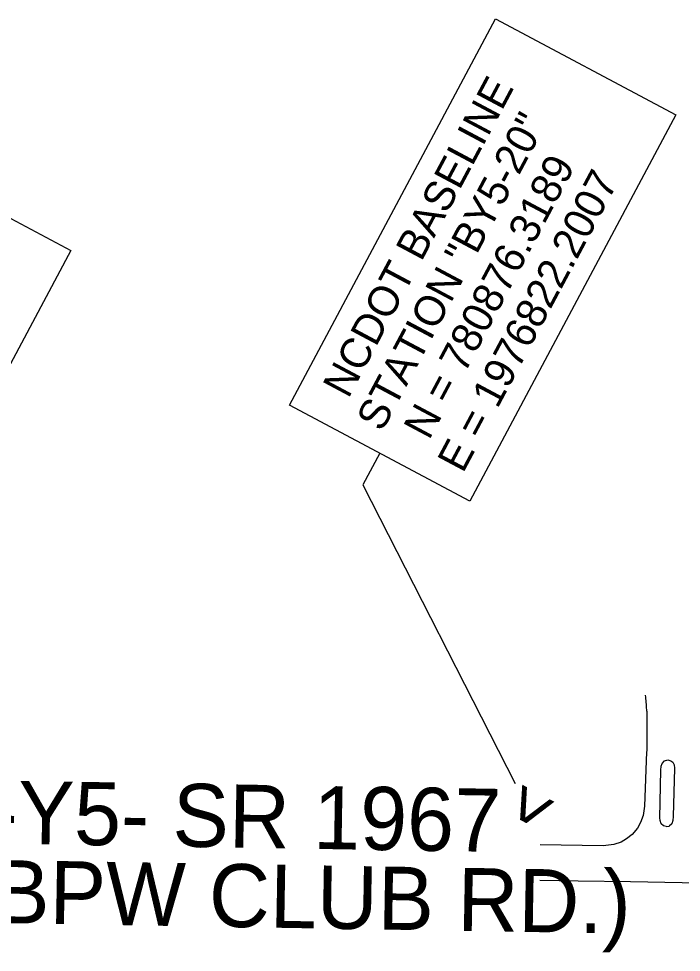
# Model space of a CAD drawing. Extents: x 1970823 to 1988115, y 770601 to 786368.
# Drawn here: x 1976409 to 1976934, y 780788 to 781528 of the extents above; entities that cross this region are included whole.
import ezdxf

# ---------------------------------------------------------------- set-up
doc = ezdxf.new("R2010")
doc.units = 0
for name, color, linetype in [('CTL Sheet Text', 7, 'Continuous'), ('CTL Supplemental Horizontal and Vertical Text', 7, 'Continuous'), ('Default', 7, 'Continuous'), ('Old_Level_3', 7, 'Continuous'), ('Old_Level_57', 7, 'Continuous')]:
    doc.layers.add(name, color=color, linetype=linetype)

msp = doc.modelspace()

# ---------------------------------------------------------------- linework, layer by layer
at = {"layer": 'CTL Supplemental Horizontal and Vertical Text'}
msp.add_lwpolyline([(1976694.99, 781183.5), (1976681.53, 781158.23), (1976802.46, 780921.4)], dxfattribs=at)
at = {"layer": 'Default'}
for points in [[(1976623.51, 781221.59), (1976786.74, 781527.91), (1976929.71, 781451.73), (1976766.47, 781145.4)], [(1976144.03, 781113.94), (1976307.27, 781420.27), (1976450.23, 781344.08), (1976287, 781037.76)]]:
    msp.add_lwpolyline(points, close=True, dxfattribs=at)
at = {"layer": 'Old_Level_3'}
msp.add_line((1976922.06, 780887.4), (1976924.3, 780887.79), dxfattribs=at)
for points in [[(1976906.61, 780978.83), (1976906.63, 780948.93), (1976906.51, 780944.93)], [(1976906.51, 780946.54), (1976904.92, 780903.58), (1976903.72, 780896.03), (1976901.72, 780890.61), (1976899.15, 780886.06), (1976894.94, 780881.09), (1976890.58, 780877.73), (1976886.24, 780875.15), (1976880.45, 780873.1), (1976872.15, 780872.09), (1976822.1, 780872.92)], [(1976922.06, 780887.4), (1976919.86, 780887.92), (1976917.95, 780889.67), (1976917.11, 780892.22), (1976916.94, 780894.4), (1976917.8, 780932.23), (1976918.06, 780935.21), (1976918.72, 780937.3), (1976920.67, 780939.57), (1976923.36, 780940.36), (1976925.69, 780939.63), (1976927.21, 780938.34), (1976928.27, 780936.3), (1976928.54, 780933.73), (1976927.49, 780895.26), (1976927.32, 780892.27), (1976926.37, 780889.55), (1976924.3, 780887.79)], [(1976981.96, 780842.14), (1976934.63, 780842.9), (1976893.62, 780843.55), (1976852.33, 780844.16), (1976821.86, 780844.67)]]:
    msp.add_lwpolyline(points, dxfattribs=at)
msp.add_spline([(1976905.46, 780991.55), (1976906.38, 780980), (1976906.47, 780978.92)], degree=3, dxfattribs=at)

# ---------------------------------------------------------------- texts
at = {"layer": 'CTL Sheet Text'}
for s, p in [('-Y5- SR 1967', (1976385.66, 780874.05)), ('(BPW CLUB RD.)', (1976366.19, 780811.33))]:
    msp.add_text(s, height=50, rotation=359.03509, dxfattribs=at).set_placement(p)
at = {"layer": 'CTL Supplemental Horizontal and Vertical Text'}
for s, p in [('NCDOT BASELINE', (1976670.09, 781226.08)), ('STATION "BY5-20"', (1976696.75, 781199.56)), ('N = 780876.3189', (1976734.12, 781193.13)), ('E = 1976822.2007', (1976760.91, 781166.86))]:
    msp.add_text(s, height=24, rotation=61.94709, dxfattribs=at).set_placement(p)
at = {"layer": 'Old_Level_57'}
msp.add_text('>', height=39.13, rotation=241.9613, dxfattribs=at).set_placement((1976805.38, 780924.91))

doc.saveas('drawing.dxf')
